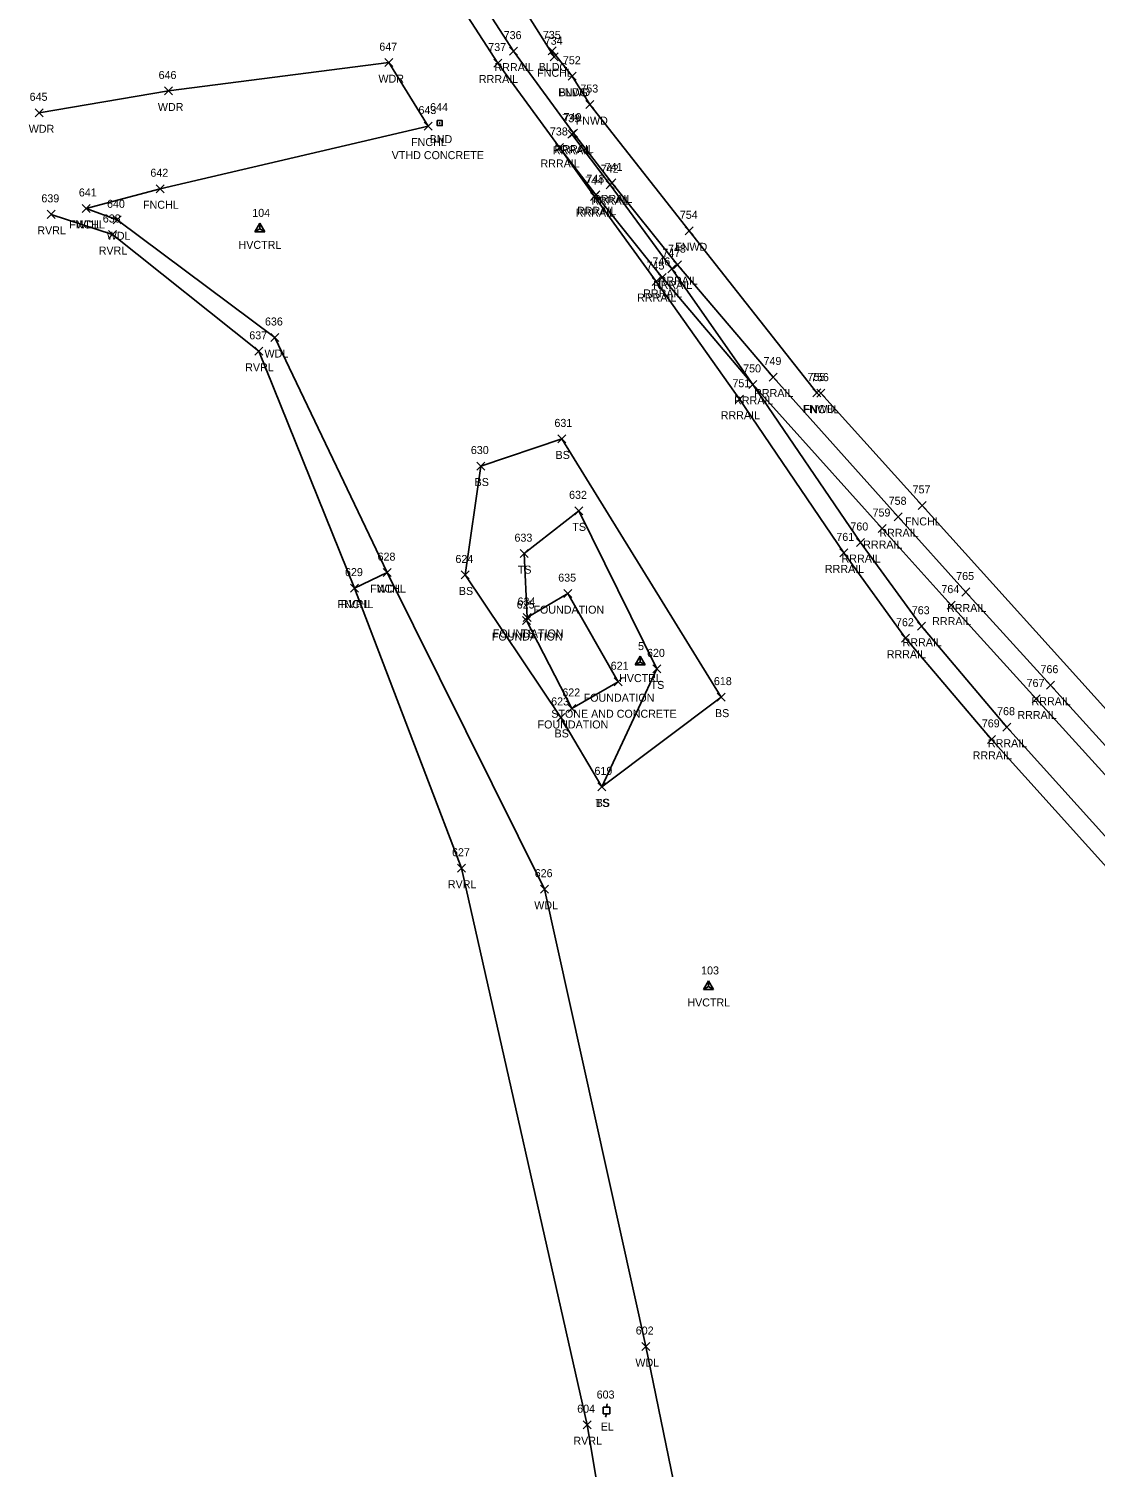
# Model space of a CAD drawing. Extents: x 1638029 to 1638889, y 618768 to 620505.
# Drawn here: x 1638085.7 to 1638352.1, y 619965.1 to 620324.6 of the extents above; entities that cross this region are included whole.
import ezdxf

# ---------------------------------------------------------------- set-up
doc = ezdxf.new("R2010")
doc.units = 0
for name, color, linetype in [('C_A', 7, 'Continuous'), ('C_I', 7, 'Continuous'), ('CPSM', 7, 'Continuous'), ('L_A', 7, 'Continuous'), ('L_C', 7, 'Continuous'), ('L_I', 7, 'Continuous'), ('L_TIC', 7, 'Continuous'), ('LAWA', 7, 'Continuous'), ('LAWE', 7, 'Continuous'), ('LBC', 7, 'Continuous'), ('LBR', 7, 'Continuous'), ('LELB', 7, 'Continuous'), ('LFNC', 7, 'Continuous'), ('M_A', 7, 'Continuous'), ('M_C', 7, 'Continuous'), ('M_I', 7, 'Continuous'), ('MHBP', 7, 'Continuous'), ('R_A', 7, 'Continuous'), ('R_I', 7, 'Continuous'), ('R_TIC', 7, 'Continuous'), ('RR', 7, 'Continuous'), ('U_A', 7, 'Continuous'), ('U_I', 7, 'Continuous'), ('UEPT', 7, 'Continuous')]:
    doc.layers.add(name, color=color, linetype=linetype)

msp = doc.modelspace()

# ---------------------------------------------------------------- linework, layer by layer
at = {"layer": 'CPSM'}
for p, q in [((1638142.12, 620273.86), (1638143.37, 620276.03)), ((1638144.62, 620273.86), (1638143.37, 620276.03)), ((1638143.37, 620274.58), (1638143.37, 620276.03)), ((1638142.12, 620273.86), (1638143.37, 620274.58)), ((1638142.12, 620273.86), (1638144.62, 620273.86)), ((1638143.37, 620274.58), (1638143.37, 620274.58)), ((1638143.37, 620274.58), (1638144.62, 620273.86)), ((1638237.2, 620165.61), (1638238.45, 620167.78)), ((1638239.7, 620165.61), (1638238.45, 620167.78)), ((1638238.45, 620166.33), (1638238.45, 620167.78)), ((1638237.2, 620165.61), (1638238.45, 620166.33)), ((1638237.2, 620165.61), (1638239.7, 620165.61)), ((1638238.45, 620166.33), (1638238.45, 620166.33)), ((1638238.45, 620166.33), (1638239.7, 620165.61)), ((1638254.26, 620084.55), (1638255.51, 620086.72)), ((1638254.26, 620084.55), (1638255.51, 620085.28)), ((1638254.26, 620084.55), (1638256.76, 620084.55)), ((1638256.76, 620084.55), (1638255.51, 620086.72)), ((1638255.51, 620085.28), (1638255.51, 620086.72)), ((1638255.51, 620085.28), (1638255.51, 620085.28)), ((1638255.51, 620085.28), (1638256.76, 620084.55))]:
    msp.add_line(p, q, dxfattribs=at)
at = {"layer": 'L_TIC'}
for points in [[(1638215.46, 620318.04), (1638217.46, 620320.04)], [(1638217.46, 620318.04), (1638215.46, 620320.04)], [(1638215.93, 620316.58), (1638217.93, 620318.58)], [(1638217.93, 620316.58), (1638215.93, 620318.58)], [(1638174.65, 620315.11), (1638176.65, 620317.11)], [(1638176.65, 620315.11), (1638174.65, 620317.11)], [(1638220.46, 620311.71), (1638222.46, 620313.71)], [(1638222.46, 620311.71), (1638220.46, 620313.71)], [(1638220.46, 620311.71), (1638222.46, 620313.71)], [(1638222.46, 620311.71), (1638220.46, 620313.71)], [(1638119.55, 620308.03), (1638121.55, 620310.03)], [(1638121.55, 620308.03), (1638119.55, 620310.03)], [(1638087.28, 620302.58), (1638089.28, 620304.58)], [(1638089.28, 620302.58), (1638087.28, 620304.58)], [(1638224.83, 620304.64), (1638226.83, 620306.64)], [(1638226.83, 620304.64), (1638224.83, 620306.64)], [(1638184.43, 620299.27), (1638186.43, 620301.27)], [(1638186.43, 620299.27), (1638184.43, 620301.27)], [(1638117.45, 620283.6), (1638119.45, 620285.6)], [(1638119.45, 620283.6), (1638117.45, 620285.6)], [(1638090.23, 620277.21), (1638092.23, 620279.21)], [(1638092.23, 620277.21), (1638090.23, 620279.21)], [(1638099.01, 620278.68), (1638101.01, 620280.68)], [(1638101.01, 620278.68), (1638099.01, 620280.68)], [(1638099.01, 620278.68), (1638101.01, 620280.68)], [(1638101.01, 620278.68), (1638099.01, 620280.68)], [(1638106.71, 620275.84), (1638108.71, 620277.84)], [(1638108.71, 620275.84), (1638106.71, 620277.84)], [(1638249.69, 620273.09), (1638251.69, 620275.09)], [(1638251.69, 620273.09), (1638249.69, 620275.09)], [(1638105.56, 620272.17), (1638107.56, 620274.17)], [(1638107.56, 620272.17), (1638105.56, 620274.17)], [(1638146.13, 620246.43), (1638148.13, 620248.43)], [(1638148.13, 620246.43), (1638146.13, 620248.43)], [(1638142.16, 620242.98), (1638144.16, 620244.98)], [(1638144.16, 620242.98), (1638142.16, 620244.98)], [(1638281.56, 620232.6), (1638283.56, 620234.6)], [(1638283.56, 620232.6), (1638281.56, 620234.6)], [(1638282.51, 620232.52), (1638284.51, 620234.52)], [(1638284.51, 620232.52), (1638282.51, 620234.52)], [(1638217.83, 620221.09), (1638219.83, 620223.09)], [(1638219.83, 620221.09), (1638217.83, 620223.09)], [(1638197.61, 620214.31), (1638199.61, 620216.31)], [(1638199.61, 620214.31), (1638197.61, 620216.31)], [(1638307.83, 620204.48), (1638309.83, 620206.48)], [(1638309.83, 620204.48), (1638307.83, 620206.48)], [(1638222.06, 620203.12), (1638224.06, 620205.12)], [(1638224.06, 620203.12), (1638222.06, 620205.12)], [(1638208.42, 620192.42), (1638210.42, 620194.42)], [(1638210.42, 620192.42), (1638208.42, 620194.42)], [(1638174.21, 620187.68), (1638176.21, 620189.68)], [(1638176.21, 620187.68), (1638174.21, 620189.68)], [(1638174.21, 620187.68), (1638176.21, 620189.68)], [(1638176.21, 620187.68), (1638174.21, 620189.68)], [(1638193.67, 620187.1), (1638195.67, 620189.1)], [(1638195.67, 620187.1), (1638193.67, 620189.1)], [(1638166.07, 620183.81), (1638168.07, 620185.81)], [(1638168.07, 620183.81), (1638166.07, 620185.81)], [(1638166.07, 620183.81), (1638168.07, 620185.81)], [(1638168.07, 620183.81), (1638166.07, 620185.81)], [(1638219.35, 620182.43), (1638221.35, 620184.43)], [(1638221.35, 620182.43), (1638219.35, 620184.43)], [(1638208.98, 620175.71), (1638210.98, 620177.71)], [(1638210.98, 620175.71), (1638208.98, 620177.71)], [(1638209.19, 620176.47), (1638211.19, 620178.47)], [(1638211.19, 620176.47), (1638209.19, 620178.47)], [(1638209.19, 620176.47), (1638211.19, 620178.47)], [(1638211.19, 620176.47), (1638209.19, 620178.47)], [(1638241.61, 620163.63), (1638243.61, 620165.63)], [(1638243.61, 620163.63), (1638241.61, 620165.63)], [(1638231.9, 620160.42), (1638233.9, 620162.42)], [(1638233.9, 620160.42), (1638231.9, 620162.42)], [(1638257.67, 620156.57), (1638259.67, 620158.57)], [(1638259.67, 620156.57), (1638257.67, 620158.57)], [(1638217.58, 620151.5), (1638219.58, 620153.5)], [(1638219.58, 620151.5), (1638217.58, 620153.5)], [(1638220.37, 620153.74), (1638222.37, 620155.74)], [(1638222.37, 620153.74), (1638220.37, 620155.74)], [(1638227.85, 620134.15), (1638229.85, 620136.15)], [(1638229.85, 620134.15), (1638227.85, 620136.15)], [(1638227.85, 620134.15), (1638229.85, 620136.15)], [(1638229.85, 620134.15), (1638227.85, 620136.15)], [(1638192.81, 620113.82), (1638194.81, 620115.82)], [(1638194.81, 620113.82), (1638192.81, 620115.82)], [(1638213.52, 620108.58), (1638215.52, 620110.58)], [(1638215.52, 620108.58), (1638213.52, 620110.58)], [(1638238.8, 619994.3), (1638240.8, 619996.3)], [(1638240.8, 619994.3), (1638238.8, 619996.3)], [(1638224.17, 619974.77), (1638226.17, 619976.77)], [(1638226.17, 619974.77), (1638224.17, 619976.77)]]:
    msp.add_lwpolyline(points, dxfattribs=at)
at = {"layer": 'LAWA'}
for points in [[(1638088.28, 620303.58), (1638120.55, 620309.03), (1638175.65, 620316.11)], [(1638175.65, 620316.11), (1638185.43, 620300.27)], [(1638270.16, 619852.57), (1638251.15, 619940.17), (1638239.8, 619995.3), (1638214.52, 620109.58), (1638175.21, 620188.68), (1638147.13, 620247.43), (1638107.71, 620276.84), (1638100.01, 620279.68)]]:
    msp.add_lwpolyline(points, dxfattribs=at)
at = {"layer": 'LAWE'}
msp.add_lwpolyline([(1638288.08, 619714.92), (1638291.39, 619757.05), (1638286.53, 619767.43), (1638252.82, 619843.75), (1638232.19, 619934.04), (1638225.17, 619975.77), (1638193.81, 620114.82), (1638167.07, 620184.81), (1638143.16, 620243.98), (1638106.56, 620273.17), (1638091.23, 620278.21)], dxfattribs=at)
at = {"layer": 'LBC'}
msp.add_lwpolyline([(1638216.46, 620319.04), (1638221.46, 620312.71)], dxfattribs=at)
at = {"layer": 'LBR'}
for points in [[(1638232.9, 620161.42), (1638221.37, 620154.74), (1638209.98, 620176.71), (1638210.19, 620177.47), (1638220.35, 620183.43)], [(1638220.35, 620183.43), (1638232.9, 620161.42)]]:
    msp.add_lwpolyline(points, dxfattribs=at)
at = {"layer": 'LELB'}
for points in [[(1638258.67, 620157.57), (1638228.85, 620135.15), (1638218.58, 620152.5), (1638194.67, 620188.1), (1638198.61, 620215.31), (1638218.83, 620222.09)], [(1638218.83, 620222.09), (1638258.67, 620157.57)], [(1638228.85, 620135.15), (1638242.61, 620164.63), (1638223.06, 620204.12), (1638209.42, 620193.42), (1638210.19, 620177.47)]]:
    msp.add_lwpolyline(points, dxfattribs=at)
at = {"layer": 'LFNC'}
for points in [[(1638248.78, 620387.73), (1638197.3, 620348.76), (1638216.93, 620317.58)], [(1638221.46, 620312.71), (1638225.83, 620305.64), (1638250.69, 620274.09), (1638282.56, 620233.6)], [(1638100.01, 620279.68), (1638118.45, 620284.6), (1638185.43, 620300.27)], [(1638283.51, 620233.52), (1638308.83, 620205.48), (1638408.62, 620094.82), (1638469.31, 620027.58)], [(1638175.21, 620188.68), (1638167.07, 620184.81)]]:
    msp.add_lwpolyline(points, dxfattribs=at)
at = {"layer": 'MHBP'}
msp.add_lwpolyline([(1638187.7, 620301.63), (1638188.95, 620301.63), (1638188.95, 620300.38), (1638187.7, 620300.38)], close=True, dxfattribs=at)
msp.add_circle((1638188.33, 620301), 0.0833, dxfattribs=at)
at = {"layer": 'R_TIC'}
for points in [[(1638205.73, 620317.99), (1638207.73, 620319.99)], [(1638207.73, 620317.99), (1638205.73, 620319.99)], [(1638201.82, 620315.02), (1638203.82, 620317.02)], [(1638203.82, 620315.02), (1638201.82, 620317.02)], [(1638220.31, 620297.23), (1638222.31, 620299.23)], [(1638222.31, 620297.23), (1638220.31, 620299.23)], [(1638220.73, 620297.51), (1638222.73, 620299.51)], [(1638222.73, 620297.51), (1638220.73, 620299.51)], [(1638217.22, 620293.92), (1638219.22, 620295.92)], [(1638219.22, 620293.92), (1638217.22, 620295.92)], [(1638217.22, 620293.92), (1638219.22, 620295.92)], [(1638219.22, 620293.92), (1638217.22, 620295.92)], [(1638229.93, 620284.59), (1638231.93, 620286.59)], [(1638231.93, 620284.59), (1638229.93, 620286.59)], [(1638230.34, 620285.06), (1638232.34, 620287.06)], [(1638232.34, 620285.06), (1638230.34, 620287.06)], [(1638226.01, 620281.65), (1638228.01, 620283.65)], [(1638228.01, 620281.65), (1638226.01, 620283.65)], [(1638226.34, 620282.09), (1638228.34, 620284.09)], [(1638228.34, 620282.09), (1638226.34, 620284.09)], [(1638245.32, 620263.59), (1638247.32, 620265.59)], [(1638247.32, 620263.59), (1638245.32, 620265.59)], [(1638246.72, 620264.63), (1638248.72, 620266.63)], [(1638248.72, 620264.63), (1638246.72, 620266.63)], [(1638241.37, 620260.41), (1638243.37, 620262.41)], [(1638243.37, 620260.41), (1638241.37, 620262.41)], [(1638242.87, 620261.45), (1638244.87, 620263.45)], [(1638244.87, 620261.45), (1638242.87, 620263.45)], [(1638265.59, 620234.71), (1638267.59, 620236.71)], [(1638267.59, 620234.71), (1638265.59, 620236.71)], [(1638265.59, 620234.71), (1638267.59, 620236.71)], [(1638267.59, 620234.71), (1638265.59, 620236.71)], [(1638270.6, 620236.56), (1638272.6, 620238.56)], [(1638272.6, 620236.56), (1638270.6, 620238.56)], [(1638262.25, 620231.01), (1638264.25, 620233.01)], [(1638264.25, 620231.01), (1638262.25, 620233.01)], [(1638301.87, 620201.63), (1638303.87, 620203.63)], [(1638303.87, 620201.63), (1638301.87, 620203.63)], [(1638297.84, 620198.7), (1638299.84, 620200.7)], [(1638299.84, 620198.7), (1638297.84, 620200.7)], [(1638292.43, 620195.21), (1638294.43, 620197.21)], [(1638294.43, 620195.21), (1638292.43, 620197.21)], [(1638288.27, 620192.61), (1638290.27, 620194.61)], [(1638290.27, 620192.61), (1638288.27, 620194.61)], [(1638318.77, 620182.84), (1638320.77, 620184.84)], [(1638320.77, 620182.84), (1638318.77, 620184.84)], [(1638315.08, 620179.56), (1638317.08, 620181.56)], [(1638317.08, 620179.56), (1638315.08, 620181.56)], [(1638307.67, 620174.28), (1638309.67, 620176.28)], [(1638309.67, 620174.28), (1638307.67, 620176.28)], [(1638303.74, 620171.29), (1638305.74, 620173.29)], [(1638305.74, 620171.29), (1638303.74, 620173.29)], [(1638339.9, 620159.55), (1638341.9, 620161.55)], [(1638341.9, 620159.55), (1638339.9, 620161.55)], [(1638336.37, 620156.11), (1638338.37, 620158.11)], [(1638338.37, 620156.11), (1638336.37, 620158.11)], [(1638329, 620149.06), (1638331, 620151.06)], [(1638331, 620149.06), (1638329, 620151.06)], [(1638325.19, 620146.02), (1638327.19, 620148.02)], [(1638327.19, 620146.02), (1638325.19, 620148.02)]]:
    msp.add_lwpolyline(points, dxfattribs=at)
at = {"layer": 'RR'}
for points in [[(1638112.47, 620498.54), (1638121.85, 620470.07), (1638132.7, 620441.63), (1638142.09, 620420.29), (1638158.38, 620387.98), (1638174.67, 620359.55), (1638202.82, 620316.02), (1638218.22, 620294.92), (1638227.34, 620283.09), (1638243.87, 620262.45), (1638266.59, 620235.71), (1638298.84, 620199.7), (1638316.08, 620180.56), (1638337.37, 620157.11), (1638394.65, 620093.98), (1638469.89, 620011.06), (1638526.76, 619948.51), (1638573.25, 619897.28), (1638598.73, 619868.77), (1638625.03, 619838.36), (1638644.96, 619812.19)], [(1638117.2, 620500.03), (1638126.53, 620471.54), (1638137.23, 620443.64), (1638146.58, 620422.4), (1638162.72, 620390.25), (1638178.78, 620362.34), (1638206.73, 620318.99), (1638221.73, 620298.51), (1638231.34, 620286.06), (1638247.72, 620265.63), (1638271.6, 620237.56), (1638302.87, 620202.63), (1638319.77, 620183.84), (1638340.9, 620160.55), (1638398.39, 620097.17), (1638473.27, 620014.71), (1638530.28, 619952.03), (1638576.7, 619900.87), (1638602.43, 619872.23), (1638628.75, 619841.68), (1638648.78, 619815.3)], [(1638221.31, 620298.23), (1638230.93, 620285.59), (1638246.32, 620264.59), (1638266.59, 620235.71), (1638293.43, 620196.21), (1638308.67, 620175.28), (1638330, 620150.06), (1638386.57, 620087.37), (1638462.88, 620003.45), (1638518.49, 619941.93), (1638565.29, 619889.65), (1638590.21, 619860.51), (1638615.55, 619828.52), (1638634.05, 619803.38)], [(1638218.22, 620294.92), (1638227.01, 620282.65), (1638242.37, 620261.41), (1638263.25, 620232.01), (1638289.27, 620193.61), (1638304.74, 620172.29), (1638326.19, 620147.02), (1638382.95, 620083.95), (1638459.2, 620000.01), (1638514.66, 619938.83), (1638562.01, 619885.9), (1638586.02, 619857.93), (1638612.02, 619825.03), (1638629.76, 619800.91)]]:
    msp.add_lwpolyline(points, dxfattribs=at)
at = {"layer": 'UEPT'}
for p, q in [((1638229.19, 619978.47), (1638229.19, 619980.13)), ((1638229.19, 619980.13), (1638230.86, 619980.13)), ((1638230.19, 619980.97), (1638230.03, 619980.13)), ((1638230.86, 619980.13), (1638230.86, 619978.47)), ((1638230.86, 619978.47), (1638229.19, 619978.47)), ((1638229.78, 619977.63), (1638230.03, 619978.47)), ((1638230.03, 619979.3), (1638230.03, 619979.3))]:
    msp.add_line(p, q, dxfattribs=at)

# ---------------------------------------------------------------- texts
at = {"layer": 'C_A'}
for p in [(1638138.06, 620269.58), (1638233.14, 620161.33), (1638250.2, 620080.28)]:
    msp.add_text('HVCTRL', height=2, dxfattribs=at).set_placement(p)
at = {"layer": 'C_I'}
for s, p in [('104', (1638141.5, 620277.58)), ('5', (1638237.88, 620169.33)), ('103', (1638253.64, 620088.28))]:
    msp.add_text(s, height=2, dxfattribs=at).set_placement(p)
at = {"layer": 'L_A'}
for s, p in [('FNCHL', (1638212.68, 620312.58)), ('BLDG', (1638213.05, 620314.04)), ('WDR', (1638173.02, 620311.11)), ('FNWD', (1638217.92, 620307.71)), ('BLDG', (1638218.05, 620307.71)), ('WDR', (1638117.91, 620304.03)), ('WDR', (1638085.65, 620298.58)), ('FNWD', (1638222.3, 620300.64)), ('FNCHL', (1638181.17, 620295.27)), ('FNCHL', (1638114.2, 620279.6)), ('RVRL', (1638087.8, 620273.21)), ('FNCHL', (1638095.76, 620274.68)), ('WDL', (1638097.43, 620274.68)), ('WDL', (1638105.13, 620271.84)), ('FNWD', (1638247.15, 620269.09)), ('RVRL', (1638103.13, 620268.17)), ('WDL', (1638144.55, 620242.43)), ('RVRL', (1638139.73, 620238.98)), ('FNWD', (1638279.03, 620228.6)), ('FNCHL', (1638279.25, 620228.52)), ('BS', (1638217.27, 620217.09)), ('BS', (1638197.05, 620210.31)), ('TS', (1638221.47, 620199.12)), ('FNCHL', (1638304.58, 620200.48)), ('TS', (1638207.83, 620188.42)), ('FNCHL', (1638170.96, 620183.68)), ('WDL', (1638172.63, 620183.68)), ('BS', (1638193.11, 620183.1)), ('FNCHL', (1638162.82, 620179.81)), ('RVRL', (1638163.64, 620179.81)), ('FOUNDATION', (1638211.74, 620178.43)), ('FOUNDATION', (1638201.59, 620172.47)), ('TS', (1638208.6, 620172.47)), ('FOUNDATION', (1638201.37, 620171.71)), ('TS', (1638241.02, 620159.63)), ('FOUNDATION', (1638224.29, 620156.42)), ('BS', (1638257.11, 620152.57)), ('FOUNDATION', (1638212.77, 620149.74)), ('BS', (1638217.02, 620147.5)), ('TS', (1638227.26, 620130.15)), ('BS', (1638227.3, 620130.15)), ('RVRL', (1638190.37, 620109.82)), ('WDL', (1638211.94, 620104.58)), ('WDL', (1638237.21, 619990.3)), ('RVRL', (1638221.73, 619970.77))]:
    msp.add_text(s, height=2, dxfattribs=at).set_placement(p)
at = {"layer": 'L_C'}
msp.add_text('STONE AND CONCRETE', height=2, dxfattribs=at).set_placement((1638216.2, 620152.42))
at = {"layer": 'L_I'}
for s, p in [('735', (1638214.1, 620322.04)), ('734', (1638214.57, 620320.58)), ('647', (1638173.24, 620319.11)), ('752', (1638219.1, 620315.71)), ('752', (1638219.1, 620315.71)), ('646', (1638118.09, 620312.03)), ('753', (1638223.47, 620308.64)), ('645', (1638085.87, 620306.58)), ('643', (1638183.02, 620303.27)), ('642', (1638116.04, 620287.6)), ('639', (1638088.81, 620281.21)), ('641', (1638098.17, 620282.68)), ('641', (1638098.17, 620282.68)), ('640', (1638105.21, 620279.84)), ('754', (1638248.32, 620277.09)), ('638', (1638104.15, 620276.17)), ('636', (1638144.67, 620250.43)), ('637', (1638140.75, 620246.98)), ('755', (1638280.2, 620236.6)), ('756', (1638281.09, 620236.52)), ('631', (1638216.99, 620225.09)), ('630', (1638196.11, 620218.31)), ('757', (1638306.47, 620208.48)), ('632', (1638220.65, 620207.12)), ('633', (1638207.01, 620196.42)), ('628', (1638172.8, 620191.68)), ('628', (1638172.8, 620191.68)), ('624', (1638192.26, 620191.1)), ('629', (1638164.66, 620187.81)), ('629', (1638164.66, 620187.81)), ('635', (1638217.94, 620186.43)), ('625', (1638207.57, 620179.71)), ('634', (1638207.78, 620180.47)), ('634', (1638207.78, 620180.47)), ('620', (1638240.12, 620167.63)), ('621', (1638231.05, 620164.42)), ('622', (1638218.96, 620157.74)), ('618', (1638256.83, 620160.57)), ('623', (1638216.17, 620155.5)), ('619', (1638227, 620138.15)), ('619', (1638227, 620138.15)), ('627', (1638191.4, 620117.82)), ('626', (1638212.06, 620112.58)), ('602', (1638237.31, 619998.3)), ('604', (1638222.68, 619978.77))]:
    msp.add_text(s, height=2, dxfattribs=at).set_placement(p)
at = {"layer": 'M_A'}
msp.add_text('BND', height=2, dxfattribs=at).set_placement((1638185.81, 620296))
at = {"layer": 'M_C'}
msp.add_text('VTHD CONCRETE', height=2, dxfattribs=at).set_placement((1638176.34, 620292))
at = {"layer": 'M_I'}
msp.add_text('644', height=2, dxfattribs=at).set_placement((1638185.92, 620304))
at = {"layer": 'R_A'}
for p in [(1638202.02, 620313.99), (1638198.11, 620311.02), (1638216.6, 620293.23), (1638217.02, 620293.51), (1638213.51, 620289.92), (1638213.51, 620289.92), (1638226.22, 620280.59), (1638226.63, 620281.06), (1638222.3, 620277.65), (1638222.63, 620278.09), (1638241.61, 620259.59), (1638243.01, 620260.63), (1638237.66, 620256.41), (1638239.16, 620257.45), (1638261.88, 620230.71), (1638261.88, 620230.71), (1638266.89, 620232.56), (1638258.54, 620227.01), (1638298.16, 620197.63), (1638294.13, 620194.7), (1638288.72, 620191.21), (1638284.56, 620188.61), (1638315.07, 620178.84), (1638311.37, 620175.56), (1638303.97, 620170.28), (1638300.03, 620167.29), (1638336.19, 620155.55), (1638332.66, 620152.11), (1638325.29, 620145.06), (1638321.48, 620142.02)]:
    msp.add_text('RRRAIL', height=2, dxfattribs=at).set_placement(p)
at = {"layer": 'R_I'}
for s, p in [('736', (1638204.31, 620321.99)), ('737', (1638200.46, 620319.02)), ('740', (1638219.28, 620301.51)), ('738', (1638215.86, 620297.92)), ('738', (1638215.86, 620297.92)), ('739', (1638218.94, 620301.23)), ('742', (1638228.57, 620288.59)), ('741', (1638229.55, 620289.06)), ('744', (1638224.65, 620285.65)), ('743', (1638224.98, 620286.09)), ('746', (1638241.45, 620265.45)), ('747', (1638243.96, 620267.59)), ('748', (1638245.36, 620268.63)), ('745', (1638240.01, 620264.41)), ('749', (1638269.23, 620240.56)), ('750', (1638264.14, 620238.71)), ('750', (1638264.14, 620238.71)), ('751', (1638261.46, 620235.01)), ('758', (1638300.5, 620205.63)), ('759', (1638296.47, 620202.7)), ('760', (1638290.93, 620199.21)), ('761', (1638287.42, 620196.61)), ('765', (1638317.37, 620186.84)), ('764', (1638313.67, 620183.56)), ('763', (1638306.27, 620178.28)), ('762', (1638302.33, 620175.29)), ('766', (1638338.43, 620163.55)), ('767', (1638334.96, 620160.11)), ('768', (1638327.59, 620153.06)), ('769', (1638323.77, 620150.02))]:
    msp.add_text(s, height=2, dxfattribs=at).set_placement(p)
at = {"layer": 'U_A'}
msp.add_text('EL', height=2, dxfattribs=at).set_placement((1638228.56, 619974.3))
at = {"layer": 'U_I'}
msp.add_text('603', height=2, dxfattribs=at).set_placement((1638227.54, 619982.3))

doc.saveas('drawing.dxf')
